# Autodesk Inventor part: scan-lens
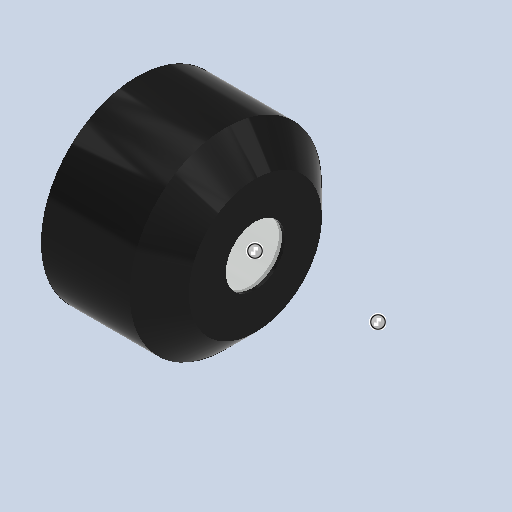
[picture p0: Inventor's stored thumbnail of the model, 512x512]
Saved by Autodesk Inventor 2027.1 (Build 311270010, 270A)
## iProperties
Created: 2026-07
Part Number: scan-lens
Material: Generic
Document SubType Name: Modeling
Designer: dunge
Density: 1 g/cm^3
Appearance: Default
Author: dunge
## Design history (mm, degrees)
derived "scan-lens-sl-simple.ipt"
  workaxis "Work Axis1"
  workpoint "Work Point1"
feature "Solid1::scan-lens-sl-simple.ipt"
tag "TaggingFeature1"
node "Finishes"
body "Solid1"
node "Finish1" dims "Finish1_Area" = 425.66002
node "Finish2" dims "Finish2_Area" = 32.42928
other parameters: "d0" = 16.51, "d4" = 0.508, "LIGHT_RADIUS" = 5.08, "d9" = 135 deg, "d10" = 0.508, "BODY_SIZE" = 20.32, "d12" = 5.08, "d13" = 0.508, "d14" = 0.508, "d15" = 0, "d16" = 0
